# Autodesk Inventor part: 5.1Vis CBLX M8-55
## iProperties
Created: 2011-01
Part Number: 5.1Vis CBLX M8-55
Document SubType Name: Modeling
Designer: eric
Density: 1 g/cm^3
Mass: 3.64172 g
Surface Area: 20.0459 cm^2
Volume: 3.64172 cm^3
Author: eric
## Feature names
1. Base1
